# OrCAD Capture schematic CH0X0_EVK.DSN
size B; title: CH0X0_EVK; rev: A1; note: 1
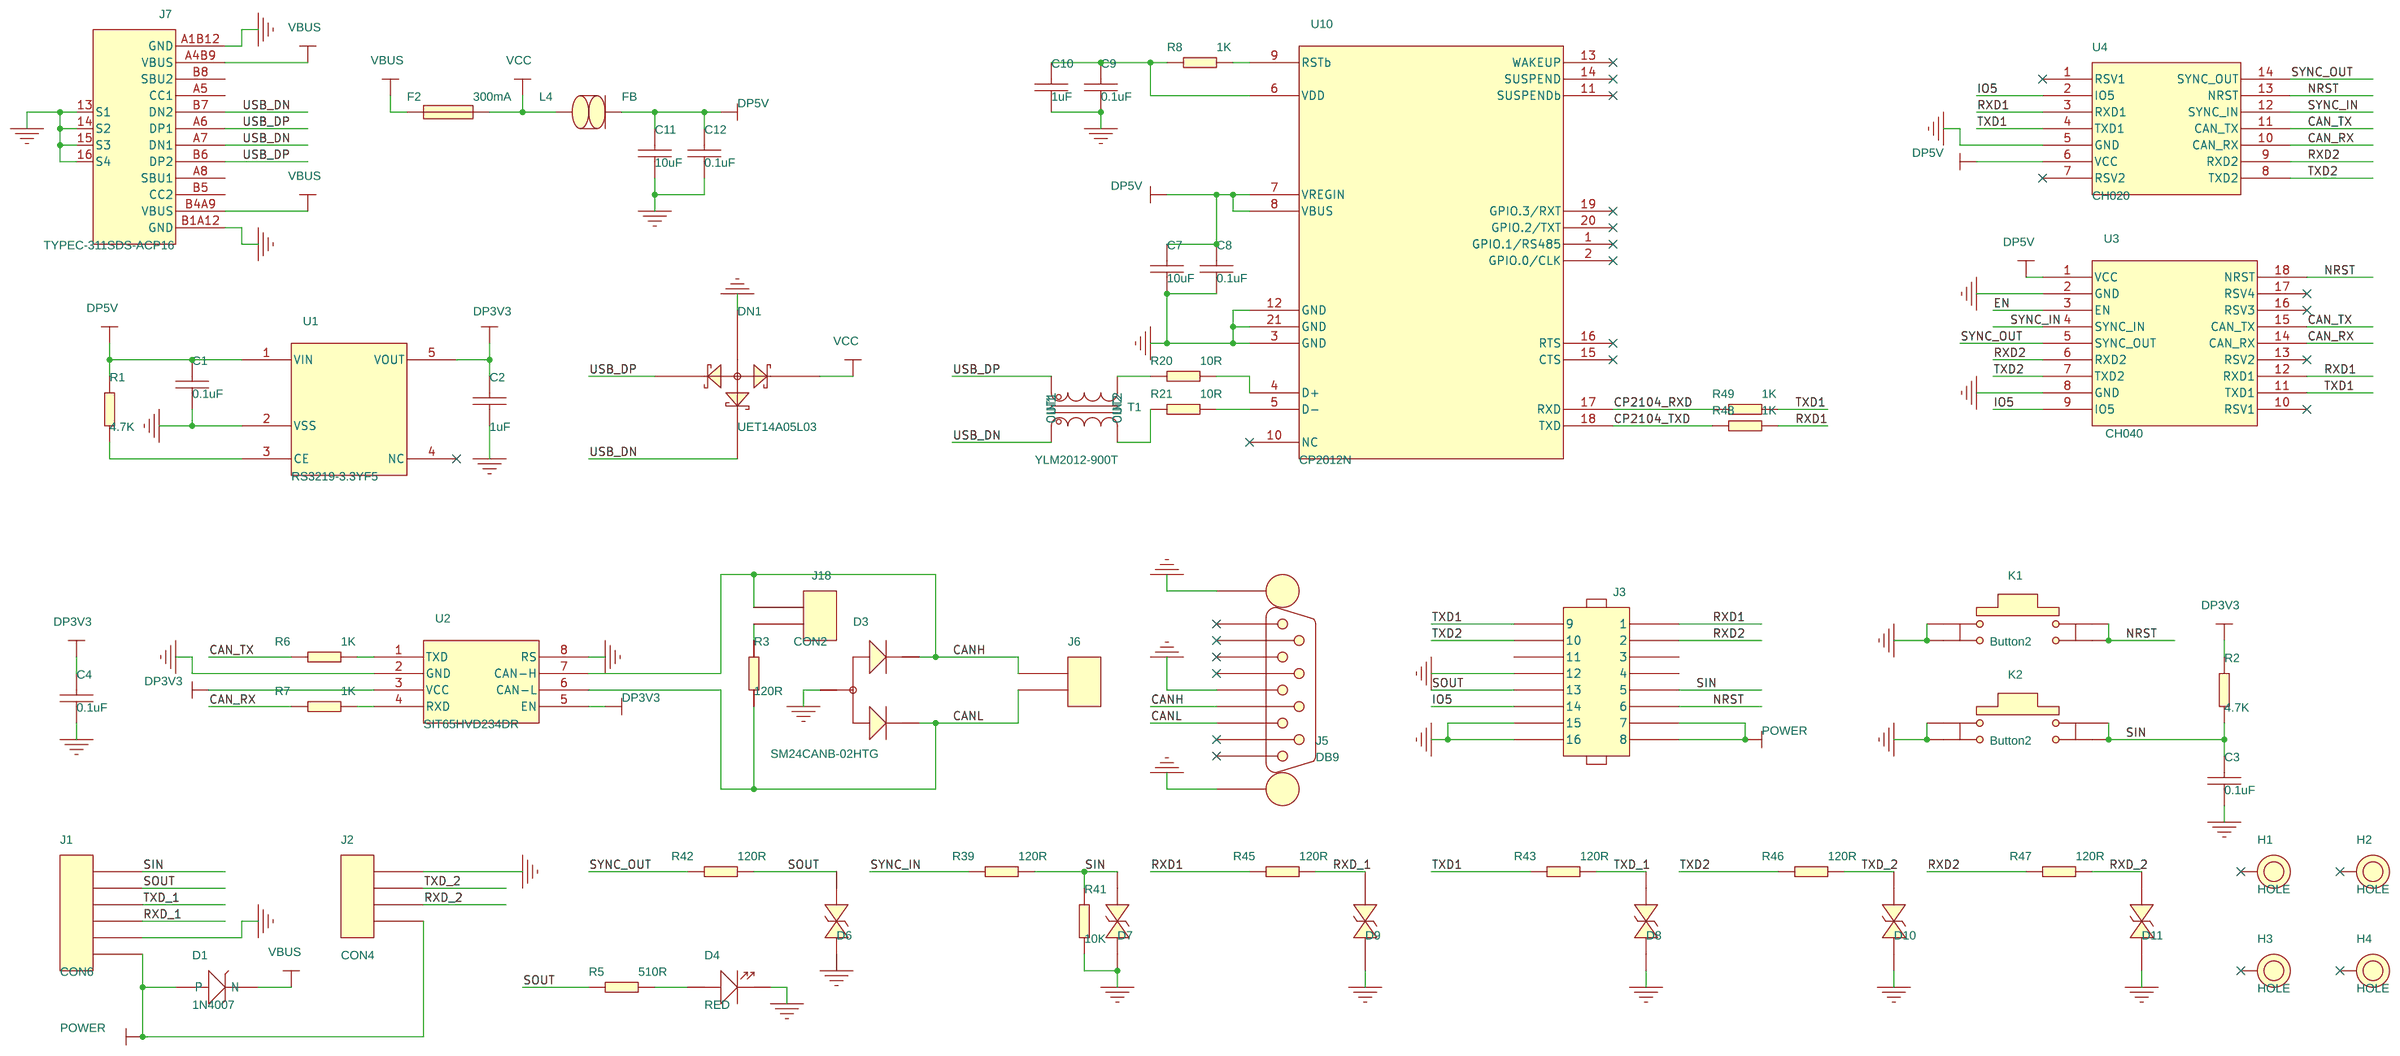
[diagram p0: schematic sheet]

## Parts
C1  0.1uF  [C0402]
C2  1uF  [C0402]
C3  0.1uF  [C0402]
C4  0.1uF  [C0402]
C7  10uF  [C0603]
C8  0.1uF  [C0402]
C9  0.1uF  [C0402]
C10  1uF  [C0402]
C11  10uF  [C0603]
C12  0.1uF  [C0402]
D1  1N4007  [DO-214AC]
D3  SM24CANB-02HTG  [SOT23-3-0_95]
D4  RED  [LED0402]
D6  SBD52C05L01  [SOD-523]
D7  SBD52C05L01  [SOD-523]
D8  SBD52C05L01  [SOD-523]
D9  SBD52C05L01  [SOD-523]
D10  SBD52C05L01  [SOD-523]
D11  SBD52C05L01  [SOD-523]
DN1  UET14A05L03  [SOT143]
F2  300mA  [F0603]
H1  HOLE  [HOLE-3-MM]
H2  HOLE  [HOLE-3-MM]
H3  HOLE  [HOLE-3-MM]
H4  HOLE  [HOLE-3-MM]
J1  CON6  [A1257WV-S-6P]
J2  CON4  [GH1X4-1_25mm_90]
J3  CONN PCB 8x2  [HEADER2X8-2_54mm]
J5  DB9  [DB9_Female]
J6  CONN PCB 2  [HEADER1X2-2_54mm]
J7  TYPEC-311SDS-ACP16  [TYPE_C_U262_161N]
J18  CON2  [HEADER1X2-2_54mm]
K1  Button2  [BUTTON_6x6]
K2  Button2  [BUTTON_6x6]
L4  FB  [L0402]
R1  4.7K  [R0402]
R2  4.7K  [R0402]
R3  120R  [R1206]
R5  510R  [R0402]
R6  1K  [R0402]
R7  1K  [R0402]
R8  1K  [R0402]
R20  10R  [R0402]
R21  10R  [R0402]
R39  120R  [R0402]
R41  10K  [R0402]
R42  120R  [R0402]
R43  120R  [R0402]
R45  120R  [R0402]
R46  120R  [R0402]
R47  120R  [R0402]
R48  1K  [R0402]
R49  1K  [R0402]
T1  YLM2012-900T  [SMD2012_4P]
U1  RS3219-3.3YF5  [SOT23-5-0_95]
U2  SIT65HVD234DR  [SOP8]
U3  CH040  [CH100_MINI]
U4  CH020  [CH010]
U10  CP2012N  [QFN-20-3x3-p0_5-cp2102n]

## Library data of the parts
C1-C4 C7-C12 = Capacity_Nonpolarity
D1 = diode
D3 = BAT54A_SOT
D4 = LED
D6-D11 = DIODE_BI-DIR_TRIG
DN1 = DS_T_CA_1
F2 = Fuse
H1-H4 = HOLE
J1 = CON6
J2 = CON4
J3 = CONN_PCB_8x2
J5 = CONN_DB9M_MTGTABS: CON 9 DB MALE 0.318 PLUG RA SHLD TH 109MIL SP 500H -- 145L; AGILE_PN: 210-82038; CAD_APPROVED: Yes; HEIGHT: 12.7MM; MFG_NAME01: REGAL ELECTRONICS; MFG_PN01: R4019-09BT; Package Type: TH; ROHS: Yes; Temp Range: -55C to +105C; Temp_Range: -55C to +105C; VOLTAGE: 300V
J6 = CONN_PCB_2
J7 = TYPE_C_12P
J18 = CON2
K1 K2 = Button2
L4 = FB
R1-R3 R5-R8 R20 R21 R39 R41-R43 R45-R49 = Res
T1 = TRNSFMR_67125450
U1 = XC6210
U2 = SN65HVD234-Q1
U3 = CH100
U4 = CH020
U10 = CP2102N-A02-GQFN20

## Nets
GND: C1.2 C2.1 C3.1 C4.1 C7.1 C8.1 C9.1 C10.1 C11.1 C12.1 D3.3 D4.2(-) D6.1 D7.1 D8.1 D9.1 D10.1 D11.1 DN1.1 J1.2 J2.4 J3.7(12) J3.13(15) J3.15(16) J5.3 J5.M1 J5.M2 J7.13(S1) J7.14(S2) J7.15(S3) J7.16(S4) J7.A1B12(GND) J7.B1A12(GND) K1.1 K1.2 K2.1 K2.2 R41.2 U1.2(VSS) U2.2(GND) U2.8(RS) U3.2(GND) U3.8(GND) U4.5(GND) U10.3(GND) U10.12(GND) U10.21(GND)
VBUS: D1.2(N) F2.1 J7.A4B9(VBUS) J7.B4A9(VBUS)
VCC: DN1.4 F2.2 L4.1
CAN_RX: R7.2 U3.14(CAN_RX) U4.10(CAN_RX)
CAN_TX: R6.2 U3.15(CAN_TX) U4.11(CAN_TX)
CANH: D3.1 J5.7 J6.1 J18.1 U2.7(CAN-H)
CANL: D3.2 J5.2 J6.2 R3.2 U2.6(CAN-L)
CC2: J7.B5(CC2)
CP2104_RXD: R49.1 U10.17(RXD)
CP2104_TXD: R48.1 U10.18(TXD)
DP3V3: C2.2 C4.2 R2.2 U1.5(VOUT) U2.3(VCC) U2.5(EN)
DP5V: C1.1 C7.2 C8.2 C11.2 C12.2 L4.2 R1.2 U1.1(VIN) U3.1(VCC) U4.6(VCC) U10.7(VREGIN) U10.8(VBUS)
EN: U3.3(EN)
IO5: J3.11(14) U3.9(IO5) U4.2(IO5)
NRST: J3.12(6) K1.3 K1.4 U3.18(NRST) U4.13(NRST)
POWER: D1.1(P) J1.1 J2.1 J3.14(7) J3.16(8)
RXD1: J3.2(1) R45.2 R48.2 U3.12(RXD1) U4.3(RXD1)
RXD2: J3.4(2) R47.2 U3.6(RXD2) U4.9(RXD2)
RXD_1: D9.2 J1.3 R45.1
RXD_2: D11.2 J2.2 R47.1
SIN: C3.2 D7.2 J1.6 J3.10(5) K2.3 K2.4 R2.1 R39.1 R41.1
SOUT: D6.2 J1.5 J3.9(13) R5.1 R42.1
SYNC_IN: R39.2 U3.4(SYNC_IN) U4.12(SYNC_IN)
SYNC_OUT: R42.2 U3.5(SYNC_OUT) U4.14(SYNC_OUT)
TXD1: J3.1(9) R43.2 R49.2 U3.11(TXD1) U4.4(TXD1)
TXD2: J3.3(10) R46.2 U3.7(TXD2) U4.8(TXD2)
TXD_1: D8.2 J1.4 R43.1
TXD_2: D10.2 J2.3 R46.1
USB_DN: DN1.3 J7.A7(DN1) J7.B7(DN2) T1.3(OUT1)
USB_DP: DN1.2 J7.A6(DP1) J7.B6(DP2) T1.1(IN1)
N1746824: D4.1(+) R5.2
N1748528: R1.1 U1.3(CE)
N1750382: R7.1 U2.4(RXD)
N1750594: R6.1 U2.1(TXD)
N1756014: C9.2 C10.2 R8.1 U10.6(VDD)
N1756148: R8.2 U10.9(RSTb)
N1756188: R20.1 T1.2(IN2)
N1756192: R21.1 T1.4(OUT2)
N1756238: R21.2 U10.5(D-)
N1756242: R20.2 U10.4(D+)
N1912221: J18.2 R3.1

Not connected (* = marked no-connect by the designer): H1 1*; H2 1*; H3 1*; H4 1*; J3 5(11) 6(3) 8(4); J5 1* 4* 5* 6* 8* 9*; J7 A5(CC1) A8(SBU1) B8(SBU2); U1 4(NC)*; U3 10(RSV1)* 13(RSV2)* 16(RSV3)* 17(RSV4)*; U4 1(RSV1)* 7(RSV2)*; U10 1(GPIO.1/RS485)* 2(GPIO.0/CLK)* 10(NC)* 11(SUSPENDb)* 13(WAKEUP)* 14(SUSPEND)* 15(CTS)* 16(RTS)* 19(GPIO.3/RXT)* 20(GPIO.2/TXT)*
